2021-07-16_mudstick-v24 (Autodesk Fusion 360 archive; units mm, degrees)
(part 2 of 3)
sketch "Sketch19" plane through (2.9, 0, 0) normal (-1, 0, 0) x axis (0, -1, 0)
  line L1 (27.1, 161.8575) -> (13.5, 161.8575)
  line L2 (30.1, 117.8575) -> (30.1, 158.8575)
  line L3 (10.5, 114.8575) -> (27.1, 114.8575)
  line L4 (10.5, 114.75) -> (10.5, 114.8575)
  line L5 (10.1, 114.75) -> (10.5, 114.75)
  line L6 (10.1, 2.0302) -> (10.1, 114.75)
  line L7 (10.5, 2.0302) -> (10.1, 2.0302)
  line L8 (10.5, -11) -> (10.5, 2.0302)
  line L9 (27.35, -11) -> (10.5, -11)
  line L10 (27.35, -7.85) -> (27.35, -11)
  line L11 (52.65, -7.85) -> (27.35, -7.85)
  line L12 (52.65, -11) -> (52.65, -7.85)
  line L13 (73, -11) -> (52.65, -11)
  line L14 (73, 233.5398) -> (73, -11)
  line L15 (52.65, 233.5398) -> (73, 233.5398)
  line L16 (52.65, 230.3898) -> (52.65, 233.5398)
  line L17 (27.35, 230.3898) -> (52.65, 230.3898)
  line L18 (27.35, 233.5398) -> (27.35, 230.3898)
  line L19 (4, 233.5398) -> (27.35, 233.5398)
  line L20 (4, 181.5398) -> (4, 233.5398)
  line L21 (7.5, 178.5398) -> (7, 178.5398)
  line L22 (10.5, 164.8575) -> (10.5, 175.5398)
  line L23 (105.1, 15.7802) -> (85.1, 15.7802)
  line L24 (105.1, 35.7802) -> (105.1, 15.7802)
  line L25 (85.1, 35.7802) -> (105.1, 35.7802)
  line L26 (85.1, 15.7802) -> (85.1, 35.7802)
  line L27 (25, 6.7802) -> (65, 6.7802)
  line L28 (105.1, 25.7802) -> (85.1, 25.7802)
  arc A1 centre (13.5, 164.8575) radius 3 clockwise from (13.5, 161.8575) to (10.5, 164.8575)
  arc A2 centre (27.1, 158.8575) radius 3 clockwise from (27.1, 161.8575) to (30.1, 158.8575)
  arc A3 centre (27.1, 117.8575) radius 3 clockwise from (30.1, 117.8575) to (27.1, 114.8575)
  arc A4 centre (7, 181.5398) radius 3 clockwise from (7, 178.5398) to (4, 181.5398)
  arc A5 centre (7.5, 175.5398) radius 3 clockwise from (7.5, 178.5398) to (10.5, 175.5398)
  circle C1 centre (12, 223.5398) radius 2.125
  circle C2 centre (16.5, -5) radius 2.125
  circle C3 centre (63.5, -5) radius 2.125
  circle C4 centre (68, 223.5398) radius 2.125
  circle C5 centre (65, 6.7802) radius 1.65
  circle C6 centre (25, 6.7802) radius 1.65
  circle C7 centre (65, 44.7802) radius 1.65
  circle C8 centre (25, 44.7802) radius 1.65
  point P43 (65, 6.7802)
  point P45 (65, 6.7802)
  point P44 (25, 6.7802)
  point P46 (25, 6.7802)
  point P47 (85.1, 25.7802)
  point P48 (105.1, 25.7802)
  point P40 (105.1, 35.7802)
  point P41 (85.1, 35.7802)
  point P42 (0.1, 1.7802)
  horizontal L23
  vertical L24
  horizontal L25
  vertical L26
  equal L25 L26
  coincident P43 P45
  coincident P44 P46
  horizontal L27
  equal C5 C6
  midpoint L26 P47
  midpoint L24 P48
  symmetric C5 L28 C7
  symmetric C6 L28 C8
  dimension "d552" distance P40 P41 = 20
  dimension "d553" distance L23 P42 = 14
  dimension "d554" diameter C5 = 3.3
  dimension "d555" distance L23 L27 = 9
  dimension "d556" distance L14 P43 = 8
  dimension "d557" distance P45 P46 = 40
  dimension "d558" distance L26 P42 = 85
extrude "Extrude33" cut sketch "Sketch19" profile of C5 C6 C7 C8 to an object
fillet "Fillet23" radius 2
offset_faces "OffsetFaces1" distance -0.25
fillet "Fillet24" radius 2
fillet "Fillet25" radius 2
fillet "Fillet26" radius 3
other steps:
joint_origin "JointOrigin1"
joint_origin "JointOrigin2"
joint_origin "JointOrigin3"
named bodies: "Home Plate", "Canister", "Nozzle", "Drive", "Drive Cap", "Drive Housing", "Outer Plunger", "Ball Screw", "Inner Plunger", "Lower Cup", "West Wing", "East Wing", "Drive Housing (1)", "Handle"

design "Mudstick Plate" references "PULL OUT DOWEL 6x16 97355A292", "Hotplate Pogo Drop", "BHCS M4x10 92095A190", "BHCS M4 x 25 92095A197"
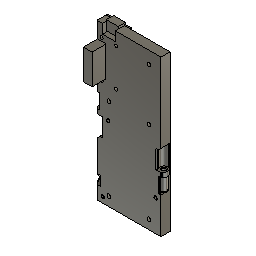
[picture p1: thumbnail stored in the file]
parameter "t_sheet_MAIN" = 7.9375 (= "5 / 16 * 1")
parameter "extrusion_w" = 20
parameter "extrusion_h" = 60
parameter "r_cutoutTool" = 2.05 (= "4.1 mm / 2")
parameter "od_bearings" = 13
parameter "id_bearings" = 4
parameter "t_bearings" = 5
parameter "preload" = 0.15
parameter "hw_m3_thru" = 3.5
parameter "hw_m3_thread" = 2.5
parameter "hw_m3_head" = 5.5
parameter "hw_m3_headheight" = 3
parameter "hw_m3_flathead" = 6
parameter "hw_m3_buttonhead" = 5.7
parameter "hw_m3_washer" = 7
parameter "hw_m3hex_d" = 5.5
parameter "hw_m3hex_t" = 4
parameter "hw_m3i_d" = 5.4
parameter "hw_m3i_l" = 3.8
parameter "hw_m3ichamfer" = 0.95 (= "( hw_m3i_d - hw_m3_thru ) / 2")
parameter "hw_m4_thru" = 4.25
parameter "hw_m4_head" = 7
parameter "hw_m4_headheight" = 4
parameter "hw_m4hex_d" = 7
parameter "hw_m4hex_t" = 5.2
parameter "hw_m4i_d" = 6
parameter "hw_m4i_l" = 4.8
parameter "hw_m4ichamfer" = 0.875 (= "( hw_m4i_d - hw_m4_thru ) / 2")
parameter "hw_m5_thread" = 4.2
parameter "hw_m5_head" = 8.5
parameter "hw_m5_washer" = 10
parameter "hw_m5_thru" = 5.25
parameter "hw_m6_thru" = 6.5
parameter "hw_m6_head" = 10
parameter "hw_m6_flathead" = 12
parameter "hw_m6_buttonhead" = 10.5
parameter "hw_m6_washer" = 12
parameter "p_belt" = 1.4
parameter "w_belt" = 10
parameter "t_belt" = 1.4
parameter "belt_pdo_toothside" = 1.15
parameter "belt_pdo_backside" = 0.25
parameter "t_m4_washer" = 0.85
parameter "flex_t" = 2.54
parameter "flex_l" = 5
parameter "t_motor_plates" = 6 comment "5/16 Phenolic"
parameter "swap_center_distance" = 40
parameter "pd_swap_drive" = 57.2958 (= "( nt_swap_drive * 2 / PI ) * 1 mm")
parameter "pd_swap_pinion" = 10.1859 (= "( nt_swap_pinion * 2 / PI ) * 1 mm")
parameter "od_mintool" = 2.1
parameter "t_sheet_THIN" = 5
parameter "c2c_spanners" = 14
parameter "c2c_height_pts" = 75
parameter "d954" = 1.7
parameter "d1221" = 5
parameter "d1747" = 9
parameter "d1748" = 5.5 (= "t_sheet_THIN + 0.5 mm")
parameter "d1761" = 2
parameter "d1917" = 5
sketch "Plan" plane through (0, 0, 0) normal (0, 0, 1) x axis (1, 0, 0)
  line L1 (-35, -5) -> (35, -5)
  line L2 (35, 5) -> (-35, 5)
  line L3 (35, -5) -> (35, 5)
  line L4 (-32.8378, -7.9826) -> (-38.2756, -10.5183)
  line L5 (-39.5997, 6.5183) -> (-32.8378, -7.9826)
  line L6 (-45.0375, 3.9826) -> (-39.5997, 6.5183)
  line L7 (-38.2756, -10.5183) -> (-45.0375, 3.9826)
  line L8 (-35.5567, -9.2505) -> (-42.3186, 5.2505)
  line L9 (-35, -3.8) -> (-35.5, -3.8)
  line L10 (-35, 3.8) -> (-35.5, 3.8)
  line L11 (-35.5, -3.8) -> (-35.5, 3.8)
  line L12 (-35.5, 0) -> (-35, 0)
  line L13 (0, -5) -> (0, 5)
  line L14 (35, 0) -> (-35, 0)
  line L15 (-33.25, 3) -> (-35, 3)
  line L16 (-30.25, -5) -> (-30.25, 0)
  line L17 (-32.75, -20) -> (-32.75, -12.9033)
  line L18 (-47.0948, -20) -> (-32.75, -20)
  line L19 (-58.5, 4.4586) -> (-47.0948, -20)
  line L20 (-58.5, 18.5) -> (-58.5, 4.4586)
  line L21 (-36.5156, 6.5) -> (0, 6.5)
  line L22 (-32.75, -12.9033) -> (-40.8544, 4.4768)
  line L23 (40, -5.1) -> (-40, -5.1)
  line L24 (40, -17.8) -> (40, -5.1)
  line L25 (-40, -17.8) -> (40, -17.8)
  line L26 (-40, -5.1) -> (-40, -17.8)
  line L27 (0, -17.8) -> (0, -5.1)
  line L28 (45, 18.5) -> (0, 18.5)
  line L29 (37.0839, 1.7621) -> (34.359, -5.7245)
  line L30 (39.0574, -7.4346) -> (34.359, -5.7245)
  line L31 (45.3388, -0.0273) -> (39.0574, -7.4346)
  line L32 (40, 4.5) -> (40, 24.5)
  line L33 (43.9547, 25.1) -> (46.9208, 5.55)
  line L34 (45, 4.5) -> (45, 18.5)
  line L35 (45, 4.5) -> (40, 4.5)
  line L36 (36, 6.5) -> (0, 6.5)
  line L37 (36, 4.5) -> (36, 6.5)
  line L38 (45, 0.5) -> (45, 4.5)
  line L39 (40, 0.5) -> (45, 0.5)
  line L40 (-58.5, 18.5) -> (0, 18.5)
  line L41 (0, 18.5) -> (0, 6.5)
  line L42 (-36.5156, 6.5) -> (-40.8544, 4.4768)
  line L43 (-35, 6.5) -> (-36.5156, 6.5)
  line L44 (-35, 18.5) -> (-35, 6.5)
  line L45 (35, 18.5) -> (35, 6.5)
  line L46 (40, 0.5) -> (36, 0.5)
  line L47 (40, 7.6754) -> (42.75, 6.0877)
  line L48 (37.25, 6.0877) -> (40, 7.6754)
  line L49 (37.25, 2.9123) -> (37.25, 6.0877)
  line L50 (40, 1.3246) -> (37.25, 2.9123)
  line L51 (42.75, 2.9123) -> (40, 1.3246)
  line L52 (42.75, 6.0877) -> (42.75, 2.9123)
  line L53 (43.1754, 24.5) -> (41.5877, 21.75)
  line L54 (41.5877, 27.25) -> (43.1754, 24.5)
  line L55 (38.4123, 27.25) -> (41.5877, 27.25)
  line L56 (36.8246, 24.5) -> (38.4123, 27.25)
  line L57 (38.4123, 21.75) -> (36.8246, 24.5)
  line L58 (41.5877, 21.75) -> (38.4123, 21.75)
  line L59 (36, 24.5) -> (36, 6.5)
  line L60 (36, 4.5) -> (36, 0.5)
  line L61 (20.3431, 18.5) -> (32.3431, 6.5)
  line L62 (-15, 11.5) -> (-35, 11.5)
  line L63 (-15, 18.5) -> (-15, 11.5)
  line L64 (-35, 2.4367) -> (-35, -5)
  line L65 (-35, 5) -> (-35, 3)
  line L66 (-33.25, -5) -> (-33.25, -3)
  line L67 (33.25, 3) -> (35, 3)
  line L68 (30.25, -5) -> (30.25, 0)
  line L69 (33.25, -5) -> (33.25, -3)
  line L70 (-35, 3) -> (-35, 2.4367)
  arc A1 centre (-32.1029, 0) radius 5.0971 clockwise from (-35.5, -3.8) to (-35.5, 3.8)
  circle C1 centre (-33.25, 0) radius 3
  circle C2 centre (33.25, 0) radius 3
  circle C3 centre (40, 4.5) radius 1.625
  circle C4 centre (40, 24.5) radius 1.625
  circle C5 centre (40, 24.5) radius 4
  circle C6 centre (40, 4.5) radius 4
  arc A2 centre (40, 4.5) radius 7 clockwise from (46.9208, 5.55) to (45.3388, -0.0273)
  circle C7 centre (-33.25, 0) radius 4.25
  circle C8 centre (-33.25, 0) radius 2.125
  circle C9 centre (33.25, 0) radius 3
  circle C10 centre (33.25, 0) radius 2.125
  circle C11 centre (33.25, 0) radius 4.25
  point P10 (-42.3186, 5.2505)
  point P11 (-35.5567, -9.2505)
  point P15 (-35, -3.8)
  point P16 (-35, 3.8)
  point P14 (-35.5, -3.8)
  point P17 (-35.5, -3.8)
  point P19 (-35.5, 0)
  point P20 (-37.2, 0)
  point P21 (0, 5)
  point P22 (0, -5)
  point P1 (0, 0)
  point P24 (35, 0)
  point P23 (-33.25, 0)
  point P25 (-35, 3)
  point P26 (-30.25, -5)
  point P27 (-38.9377, -2)
  point P41 (0, -5.1)
  point P42 (0, -17.8)
  point P52 (40, 24.5)
  point P54 (40, 24.5)
  point P49 (37.0839, 1.7621)
  point P58 (45.3388, -0.0273)
  point P51 (45.3388, -0.0273)
  point P60 (43.9547, 25.1)
  point P61 (40, 28.5)
  point P56 (40, 4.5)
  point P63 (40, 4.5)
  point P62 (45, 4.5)
  point P64 (45, 4.5)
  point P66 (36, 4.5)
  point P68 (40, 0.5)
  point P36 (0, 6.5)
  point P45 (0, 6.5)
  point P33 (-58.5, 18.5)
  point P69 (-58.5, 18.5)
  point P34 (-36.5156, 6.5)
  point P70 (-36.5156, 6.5)
  point P28 (-32.75, -12.9033)
  point P29 (-32.75, -12.9033)
  point P72 (-35, 18.5)
  point P4 (-35, 5)
  point P73 (35, 6.5)
  point P74 (35, 18.5)
  point P5 (35, 5)
  point P76 (40, 0.5)
  point P47 (40, 4.5)
  point P83 (40, 4.5)
  point P90 (40, 24.5)
  point P57 (40, 4.5)
  point P55 (40, 4.5)
  point P91 (36, 24.5)
  point P92 (36, 4.5)
  point P93 (32.3431, 6.5)
  point P94 (20.3431, 18.5)
  point P95 (-35, 11.5)
  point P97 (-15, 18.5)
  point P100 (-35, 2.4367)
  point P18 (-35, 0)
  point P101 (-33.25, 3)
  point P102 (-33.25, -3)
  point P103 (-33.25, -5)
  point P98 (-33.25, 0)
  point P104 (-30.25, 0)
  point P107 (35, 3)
  point P111 (30.25, -5)
  point P108 (33.25, 3)
  point P112 (33.25, -3)
  point P113 (33.25, -5)
  point P110 (30.25, 0)
  point P3 (-35, -5)
  point P6 (-38.2756, -10.5183)
  point P9 (-45.0375, 3.9826)
  point P8 (-39.5997, 6.5183)
  point P13 (-35.5, 3.8)
  point P37 (-40, -5.1)
  point P38 (40, -5.1)
  point P44 (33.25, 0)
  point P48 (34.359, -5.7245)
  point P50 (39.0574, -7.4346)
  point P53 (40, 24.5)
  point P67 (45, 0.5)
  point P43 (0, 18.5)
  point P79 (37.25, 6.0877)
  point P86 (41.5877, 27.25)
  point P96 (-15, 11.5)
  point P71 (-35, 6.5)
  horizontal L1
  vertical L64
  horizontal L2
  vertical L3
  perpendicular L4 L5
  parallel L4 L6
  parallel L5 L7
  midpoint L6 P10
  midpoint L4 P11
  coincident P15 L64
  perpendicular L9 L64
  coincident P16 L64
  perpendicular L10 L64
  perpendicular L10 L11
  coincident P14 P17
  perpendicular L12 L64
  midpoint L11 P19
  midpoint A1 P20
  midpoint L2 P21
  midpoint L1 P22
  midpoint P1 L13
  midpoint L3 P24
  coincident P23 L14
  coincident P25 L64
  perpendicular L15 L64
  coincident L1 P26
  perpendicular L1 L16
  midpoint L8 P27
  vertical L17
  perpendicular L17 L18
  vertical L20
  horizontal L23
  vertical L24
  horizontal L25
  vertical L26
  midpoint L23 P41
  midpoint L25 P42
  coincident P1 L27
  horizontal L21
  symmetric L13 C1 C2
  perpendicular L29 L30
  concentric C4 C5
  coincident P52 P54
  tangent C2 L29
  vertical L32
  coincident P49 C6
  coincident L31 P58
  coincident P51 P58
  tangent L31 A2
  coincident C5 P60
  tangent C5 L33
  tangent A2 L33
  coincident C5 P61
  coincident L32 P61
  perpendicular L28 L34
  coincident P56 P63
  perpendicular L32 L35
  coincident P62 P64
  perpendicular L36 L37
  coincident C6 P66
  coincident L35 P66
  perpendicular L35 L38
  perpendicular L34 L39
  coincident C6 P68
  coincident L32 P68
  coincident P36 P45
  coincident P33 P69
  perpendicular L28 L41
  coincident P1 L41
  horizontal L28
  horizontal L36
  horizontal L40
  perpendicular L5 L42
  coincident P34 P70
  parallel L8 L22
  coincident P28 P29
  parallel L8 L19
  parallel L21 L43
  coincident L40 P72
  perpendicular L40 L44
  coincident P4 L44
  coincident L36 P73
  coincident L28 P74
  perpendicular L28 L45
  coincident P5 L45
  equal C5 C6
  perpendicular L37 L46
  coincident P68 P76
  coincident P47 P83
  vertical L52
  coincident P52 P90
  horizontal L58
  coincident P57 P83
  coincident P55 P57
  coincident P47 P56
  coincident C5 P91
  perpendicular L46 L60
  coincident P66 P92
  coincident L36 P93
  coincident L28 P94
  tangent C6 L61
  coincident L44 P95
  perpendicular L41 L62
  coincident L40 P97
  perpendicular L40 L63
  tangent L5 C1
  concentric C1 C7
  concentric C1 C8
  coincident C1 P100
  collinear L64 L65
  coincident P18 L64
  coincident C1 P101
  coincident C1 P102
  coincident L1 P103
  perpendicular L1 L66
  coincident P98 L66
  coincident C1 P104
  symmetric L13 C1 C9
  symmetric L13 P25 P107
  symmetric L13 P26 P111
  symmetric L13 C7 C11
  symmetric L13 C8 C10
  symmetric L13 P101 P108
  symmetric L13 P102 P112
  symmetric L13 P103 P113
  symmetric L13 P104 P110
  dimension "d1706" distance P3 P4 = 10
  dimension "d1707" distance P6 P9 = 16
  dimension "d1708" distance P8 P9 = 6
  dimension "d1709" distance P13 P17 = 7.6
  dimension "d1710" distance P20 L64 = 2.2
  dimension "d1711" distance P13 P16 = 0.5
  dimension "d1712" distance P1 L64 = 35
  dimension "d1713" diameter C1 = 6
  dimension "d1714" distance P23 L64 = 1.75
  dimension "d1715" distance P23 L16 = 3 (= "d1713 / 2")
  dimension "d1716" distance P23 L15 = 3 (= "d1715")
  dimension "d1717" angle L8 L64 = 25
  dimension "d1723" distance L14 P27 = 2
  dimension "d1731" distance L17 L64 = 2.25
  dimension "d1732" distance L14 L18 = 20
  dimension "d1734" distance P27 L22 = 1
  dimension "d1763" distance P37 P38 = 80
  dimension "d1764" distance P41 P42 = 12.7
  dimension "d1765" distance L1 L23 = 0.1
  dimension "d1796" diameter C3 = 3.25
  dimension "d1799" distance L3 P47 = 5
  dimension "d1800" diameter C4 = 3.25
  dimension "d1802" angle L3 L29 = 20
  dimension "d1803" distance P44 L30 = 5
  dimension "d1804" distance P48 P50 = 5
  dimension "d1805" = 8.2688
  dimension "d1806" distance P47 P53 = 20
  dimension "d1808" = 1.5
  dimension "d1809" diameter C6 = 8
  dimension "d1810" distance P44 P47 = 4.5
  dimension "d1811" radius A2 = 7
  dimension "d1827" distance P67 P68 = 5
  dimension "d1955" distance L14 L21 = 6.5
  dimension "d1988" distance P36 P43 = 12
  dimension "d1989" distance P4 L42 = 2
  dimension "d1990" distance P27 L19 = 15
  dimension "d2035" distance P79 L52 = 5.5
  dimension "d2036" distance P86 L58 = 5.5
  dimension "d2063" angle L32 L61 = 45
  dimension "d2100" distance P95 P96 = 20
  dimension "d2126" distance P71 L62 = 5
  dimension "d2129" diameter C7 = 8.5
  dimension "d2130" diameter C8 = 4.25
  dimension "d2131" radius A1 = 5.0971
  dimension "d2236" distance L20 P72 = 23.5
  dimension "d523" OffsetX = 0
  dimension "d524" OffsetY = 0
  dimension "d525" OffsetZ = 0
  dimension "d526" AngleZ = 0
  dimension "d567" OffsetX = 0
  dimension "d568" OffsetY = 0
  dimension "d569" OffsetZ = 0
  dimension "d570" AngleZ = 0
  dimension "d1892" alignAngle = 180
  dimension "d1893" alignOffsetX = 0
  dimension "d1894" alignOffsetY = 0
  dimension "d1895" alignOffsetZ = 1
  dimension "d1896" radius = 1.05 (= "od_mintool / 2")
  dimension "d1897" distance = 1.05 (= "d1896")
  dimension "d1898" radius = 1.05 (= "od_mintool / 2")
  dimension "d1899" distance = 1.05 (= "d1898")
  dimension "d1900" distance = 17
  dimension "d1901" distance = 15
  dimension "d1902" ProfileOffset = 0
  dimension "d1903" Side1Offset = 0
  dimension "d1904" TaperAngle = 0
  dimension "d1905" ProfileOffset = 0
  dimension "d1906" Side1Offset = 0
  dimension "d1907" TaperAngle = 0
  dimension "d1908" ProfileOffset = 0
  dimension "d1909" Side1Offset = 0
  dimension "d1910" TaperAngle = 0
  dimension "d1911" ProfileOffset = 0
  dimension "d1912" Side1Offset = 0
  dimension "d1913" TaperAngle = 0
  dimension "d1914" Side1Offset = 0
  dimension "d1915" TaperAngle = 0
  dimension "d1916" distance = 10
  dimension "d1918" distance = 5
  dimension "d1919" distance = 25
  dimension "d1921" TaperAngle = 0
  dimension "d1922" distance = -0.075
  dimension "d1923" angle = 45
  dimension "d1924" diameter = 2.1 (= "od_mintool")
  dimension "d1925" diameter = 2.1 (= "od_mintool")
  dimension "d1926" diameter = 2.1 (= "od_mintool")
  dimension "d1927" Side1Offset = 0
  dimension "d1928" TaperAngle = 0
  dimension "d1929" ProfileOffset = 0
  dimension "d1930" Side1Offset = 0
  dimension "d1931" TaperAngle = 0
  dimension "d1932" angle = 45
  dimension "d1933" diameter = 2.1 (= "od_mintool")
  dimension "d1934" diameter = 2.1 (= "od_mintool")
  dimension "d1935" Side1Offset = 0
  dimension "d1936" TaperAngle = 0
  dimension "d1937" distance = -0.075
  dimension "d1941" Side1Offset = 0
  dimension "d1942" TaperAngle = 0
  dimension "d1943" Side1Offset = 0
  dimension "d1944" TaperAngle = 0
  dimension "d1947" alignAngle = 0
  dimension "d1948" alignOffsetX = 0
  dimension "d1949" alignOffsetY = 0
  dimension "d1950" alignOffsetZ = 0
  dimension "d1951" alignAngle = 90
  dimension "d1952" alignOffsetX = 0
  dimension "d1953" alignOffsetY = 0
  dimension "d1954" alignOffsetZ = 0
  dimension "d1958" ProfileOffset = 0
  dimension "d1959" Side1Offset = 0
  dimension "d1960" TaperAngle = 0
  dimension "d1961" distance = -0.075
  dimension "d1962" ProfileOffset = 0
  dimension "d1963" Side1Offset = 0
  dimension "d1964" TaperAngle = 0
  dimension "d1965" distance = -0.075
  dimension "d1966" distance = 67
  dimension "d1967" distance = 33
  dimension "d1968" diameter = 2.5
  dimension "d1969" distance = 4
  dimension "d1970" distance = 29
  dimension "d1971" distance = 34
  dimension "d1972" distance = 54
  dimension "d1973" distance = 4
  dimension "d1974" distance = 3
  dimension "d1975" distance = 3
  dimension "d1976" distance = 5
  dimension "d1977" distance = 5
  dimension "d1978" distance = 1
  dimension "d1979" distance = 1
  dimension "d1980" distance = 10
  dimension "d1981" distance = 10
  dimension "d1982" distance = 6
  dimension "d1983" ProfileOffset = 0
  dimension "d1984" Side1Offset = 0
  dimension "d1985" TaperAngle = 0
  dimension "d1987" Radius = 1.05 (= "od_mintool / 2")
  dimension "d1597" distance = 1.6
  dimension "d1598" distance = 67
  dimension "d1599" diameter = 4.25
  dimension "d1600" diameter = 3.3
  dimension "d1601" distance = 1
  dimension "d1602" distance = 1
  dimension "d1603" distance = 0.5
  dimension "d1604" distance = 12
  dimension "d1605" distance = 0.25
  dimension "d1606" distance = 0.25
  dimension "d1607" distance = 1
  dimension "d1608" distance = 8
  dimension "d1609" distance = 4.5
  dimension "d1610" distance = 4.5
  dimension "d1612" TaperAngle = 0
  dimension "d1613" AlongDistance = -53 (= "-20 mm - 33 mm")
  dimension "d1614" TaperAngle = 0
  dimension "d1615" ProfileOffset = 0.1
  dimension "d1616" Side1Offset = 0
  dimension "d1617" TaperAngle = 0
  dimension "d1618" leftDistance = 1
  dimension "d1619" distance = 67
  dimension "d1620" distance = 33
  dimension "d1621" distance = 0.5
  dimension "d1622" distance = 24.5
  dimension "d1623" diameter = 2.5
  dimension "d1624" distance = 4
  dimension "d1625" distance = 34
  dimension "d1626" distance = 54
  dimension "d1627" distance = 4
  dimension "d1628" distance = 29
  dimension "d1631" distance = 1
  dimension "d1633" distance = 3
  dimension "d1634" distance = 2.44 (= "d1643")
  dimension "d1635" diameter = 4
  dimension "d1636" distance = 15
  dimension "d1637" distance = 3
  dimension "d1638" distance = 15
  dimension "d1639" distance = 2
  dimension "d1640" Side1Offset = 0
  dimension "d1641" TaperAngle = 0
  dimension "d1642" distance = 2.44
  dimension "d1643" distance = 2.44
  dimension "d1644" AlongDistance = -16
  dimension "d1645" TaperAngle = 0
  dimension "d1647" Radius = 1
  dimension "d1649" Radius = 1
  dimension "d1651" Radius = 5
  dimension "d1653" Radius = 1
  dimension "d1654" diameter = 12
  dimension "d1655" Side1Offset = 0
  dimension "d1656" TaperAngle = 0
  dimension "d1658" Radius = 2
  dimension "d1659" distance = 20
  dimension "d1660" distance = 5
  dimension "d1661" distance = 5
  dimension "d981" distance = 15 (= "( 30 / 2 ) * 1 mm")
  dimension "d982" distance = 8
  dimension "d983" distance = 1.5
  dimension "d984" distance = 0.3
  dimension "d985" distance = 4
  dimension "d987" distance = 1
  dimension "d988" distance = 7.5
  dimension "d989" distance = 5
  dimension "d990" distance = 0.5
  dimension "d991" AlongAngle = 60
  dimension "d992" AgainstAngle = 60
  dimension "d993" distance = 4
  dimension "d994" angle = 60
  dimension "d995" angle = 60 (= "d994")
  dimension "d1004" diameter = 6.5
  dimension "d1005" distance = 1.5
  dimension "d1006" AlongDistance = -10
  dimension "d1007" TaperAngle = 0
  dimension "d1008" Side1Offset = 0
  dimension "d1009" TaperAngle = 0
  dimension "d1010" ProfileOffset = 0
  dimension "d1011" AlongDistance = -0.5
  dimension "d1012" TaperAngle = 0
  dimension "d1013" AlongDistance = 2.5
  dimension "d1014" TaperAngle = 0
  dimension "d1015" leftDistance = 0.25
  dimension "d1017" Radius = 1
  dimension "d1019" TotalAngle = 360
  dimension "d1020" ProfileOffset = 0
  dimension "d1021" Side1Offset = 0
  dimension "d1022" TaperAngle = 0
  dimension "d1028" angle = 25
  dimension "d1029" ProfileOffset = 0
  dimension "d1030" Side1Offset = 0
  dimension "d1031" TaperAngle = 0
  dimension "d1032" ProfileOffset = 0
  dimension "d1034" TaperAngle = 0
  dimension "d1035" Side1Offset = 0
  dimension "d1036" distance = 3
  dimension "d1037" leftDistance = 3
  dimension "d1038" rightDistance = 17.25
  dimension "d1039" Side1Offset = 0
  dimension "d1040" TaperAngle = 0
  dimension "d1042" TotalAngle = 360
  dimension "d1043" Side1Offset = 0
  dimension "d1044" TaperAngle = 2
  dimension "d1045" angle = 1
  dimension "d1047" Side1Offset = 0
  dimension "d1048" TaperAngle = 0
  dimension "d1049" distance = -1 (= "0 mm - 1 mm")
  dimension "d1051" TotalAngle = 360
  dimension "d1053" angle = 43.731
  dimension "d1054" angle = 28 (= "d1055 - d1056")
  dimension "d1055" angle = 50 (= "d1028 * 2")
  dimension "d1056" angle = 22
  dimension "d1058" Radius = 2
  dimension "d1060" Radius = 2
  dimension "d1061" alignAngle = 0
  dimension "d1062" alignOffsetX = 0
  dimension "d1063" alignOffsetY = 0
  dimension "d1064" alignOffsetZ = 0
  dimension "d1082" distance = 0.8
  dimension "d1084" distance = 0.8
  dimension "d1085" distance = 1.2
  dimension "d1086" distance = 1.2
  dimension "d1087" distance = 0.1
  dimension "d1093" Radius = 0.5
  dimension "d1095" Radius = 0.5
  dimension "d1097" Radius = 2
  dimension "d1103" distance = 1.3
  dimension "d1105" TotalAngle = 360
  dimension "d1106" distance = 2.75 (= "hw_m3hex_d / 2")
  dimension "d1107" distance = 1.75 (= "hw_m3_thru / 2")
  dimension "d1108" angle = 45
  dimension "d1109" distance = 3.6
  dimension "d1110" distance = 20
  dimension "d1111" distance = 1.7
  dimension "d1112" AlongAngle = 360
  dimension "d1113" Side1Offset = 0
  dimension "d1114" TaperAngle = 0
  dimension "d1116" TotalAngle = 360
  dimension "d1118" Radius = 2
  dimension "d1120" distance = 3.175 (= "1 / 8 * 1")
  dimension "d1121" radius = 12
  dimension "d1123" radius = 6.5
  dimension "d1124" angle = 60
  dimension "d1126" distance = 2.8797 (= "13 / 64 * 1  / 2 + 0.3 mm")
  dimension "d1127" distance = 9.5563 (= "7 / 32 * 1  + 4 mm")
  dimension "d1128" AlongDistance = -6
  dimension "d1129" diameter = 3.475 (= "1 / 8 * 1  + 0.3 mm")
  dimension "d1130" diameter = 1.7875 (= "1 / 16 * 1  + 0.2 mm")
  dimension "d1141" TwistAngle = 0
  dimension "d1142" TaperAngle = 0
  dimension "d1143" angle = 51
  dimension "d1144" distance = 2.8797 (= "d1126")
  dimension "d1145" diameter = 1.7875 (= "1 / 16 * 1  + 0.2 mm")
  dimension "d1150" TwistAngle = 0
  dimension "d1151" TaperAngle = 0
  dimension "d1152" distance = 1.7875 (= "1 / 16 * 1  + 0.2 mm")
  dimension "d1153" Side1Offset = 0
  dimension "d1154" TaperAngle = 0
  dimension "d1155" AlongDistance = -4
  dimension "d1156" TaperAngle = 0
  dimension "d1157" diameter = 5.3594 (= "13 / 64 * 1  + 0.2 mm")
  dimension "d1158" AlongDistance = 1.5
  dimension "d1159" TaperAngle = 0
  dimension "d1164" TwistAngle = 0
  dimension "d1165" TaperAngle = 0
  dimension "d1167" mirrorStitchTolerance = 0.1
  dimension "d1169" Radius = 0.4
  dimension "d1170" distance = 11
  dimension "d1171" distance = 1.0938 (= "( 1 / 16 * 1  + 0.2 mm ) / 2 + 0.2 mm")
  dimension "d1172" distance = 1.7
  dimension "d1173" distance = 1.7
  dimension "d1174" Side1Offset = 0
  dimension "d1175" TaperAngle = 0
  dimension "d1176" Side2Offset = -1
  dimension "d1177" Side2TaperAngle = 0
  dimension "d1179" mirrorStitchTolerance = 0.1
  dimension "d1181" Radius = 0.5
  dimension "d1182" alignAngle = 0
  dimension "d1183" alignOffsetX = 0
  dimension "d1184" alignOffsetY = 0
  dimension "d1185" alignOffsetZ = 0
  dimension "d1186" leftDistance = 0.75
  dimension "d1187" rightDistance = 3
  dimension "d1189" Radius = 12
  dimension "d1191" Radius = 2
  dimension "d1193" Radius = 0.5
  dimension "d1195" Radius = 0.5
  dimension "d1197" Radius = 0.5
  dimension "d1198" alignAngle = 0
  dimension "d1199" alignOffsetX = 0
  dimension "d1200" alignOffsetY = 0
  dimension "d1201" alignOffsetZ = 0
  dimension "d1202" distance = 13.5
sketch "Elevation" plane through (0, 0, 0) normal (0, 1, 0) x axis (1, 0, 0)
  line L1 (35, 0) -> (-35, 0)
  line L2 (35, -115) -> (35, 0)
  line L3 (-35, -115) -> (35, -115)
  line L4 (-35, 0) -> (-35, -115)
  line L5 (35, -10.5) -> (-35, -10.5)
  line L6 (-35, -15.5) -> (35, -15.5)
  line L7 (35, -24.5) -> (-35, -24.5)
  line L8 (-35, -29.5) -> (35, -29.5)
  line L9 (35, -85.5) -> (-35, -85.5)
  line L10 (-35, -90.5) -> (35, -90.5)
  line L11 (35, -99.5) -> (-35, -99.5)
  line L12 (-35, -104.5) -> (35, -104.5)
  line L13 (35, -40) -> (-35, -40)
  line L14 (35, -45) -> (-35, -45)
  line L15 (0, -90.5) -> (0, -99.5)
  line L16 (0, -24.5) -> (0, -15.5)
  line L17 (-35, 0) -> (35, 0)
  line L18 (0, -29.5) -> (0, -40)
  line L19 (0, -24.5) -> (0, -29.5)
  line L20 (0, -10.5) -> (0, -15.5)
  line L21 (0, -85.5) -> (0, -90.5)
  line L22 (0, -104.5) -> (0, -99.5)
  line L23 (25, -95) -> (-30, -95)
  line L24 (25, -20) -> (25, -95)
  line L25 (-30, -20) -> (25, -20)
  line L26 (-30, -95) -> (-30, -20)
  line L27 (-35, -50.5) -> (35, -50.5)
  line L28 (35, -55.5) -> (-35, -55.5)
  line L29 (0, -55.5) -> (0, -50.5)
  line L30 (0, -50.5) -> (0, -45)
  line L31 (-35.5, -78) -> (-56.5, -78)
  line L32 (-35.5, -37) -> (-35.5, -78)
  line L33 (-56.5, -37) -> (-35.5, -37)
  line L34 (-41, -82.25) -> (-51, -82.25)
  line L35 (-41, -32.75) -> (-41, -82.25)
  line L36 (-51, -32.75) -> (-41, -32.75)
  line L37 (-51, -82.25) -> (-51, -32.75)
  line L38 (-46, -57.5) -> (-46, -82.25)
  line L39 (-35.5, -57.5) -> (-46, -57.5)
  line L40 (-56.5, -85.5) -> (-56.5, -78)
  line L41 (-35, -85.5) -> (-56.5, -85.5)
  line L42 (-56.5, -29.5) -> (-35, -29.5)
  line L43 (-56.5, -37) -> (-56.5, -29.5)
  line L44 (-47.8246, -82.25) -> (-49.4123, -85)
  line L45 (-49.4123, -79.5) -> (-47.8246, -82.25)
  line L46 (-52.5877, -79.5) -> (-49.4123, -79.5)
  line L47 (-54.1754, -82.25) -> (-52.5877, -79.5)
  line L48 (-52.5877, -85) -> (-54.1754, -82.25)
  line L49 (-49.4123, -85) -> (-52.5877, -85)
  line L50 (-44.1754, -82.25) -> (-42.5877, -79.5)
  line L51 (-42.5877, -85) -> (-44.1754, -82.25)
  line L52 (-39.4123, -85) -> (-42.5877, -85)
  line L53 (-37.8246, -82.25) -> (-39.4123, -85)
  line L54 (-39.4123, -79.5) -> (-37.8246, -82.25)
  line L55 (-42.5877, -79.5) -> (-39.4123, -79.5)
  line L56 (-37.8246, -32.75) -> (-39.4123, -30)
  line L57 (-39.4123, -35.5) -> (-37.8246, -32.75)
  line L58 (-42.5877, -35.5) -> (-39.4123, -35.5)
  line L59 (-44.1754, -32.75) -> (-42.5877, -35.5)
  line L60 (-39.4123, -30) -> (-42.5877, -30)
  line L61 (-42.5877, -30) -> (-44.1754, -32.75)
  line L62 (-52.5877, -35.5) -> (-49.4123, -35.5)
  line L63 (-54.1754, -32.75) -> (-52.5877, -35.5)
  line L64 (-52.5877, -30) -> (-54.1754, -32.75)
  line L65 (-49.4123, -30) -> (-52.5877, -30)
  line L66 (-49.4123, -35.5) -> (-47.8246, -32.75)
  line L67 (-47.8246, -32.75) -> (-49.4123, -30)
  line L68 (-47, -80.75) -> (-47, -78)
  line L69 (-45, -78) -> (-45, -80.75)
  line L70 (-46, -80.75) -> (-46, -78)
  line L71 (-47, -34.25) -> (-47, -37)
  line L72 (-45, -37) -> (-45, -34.25)
  circle C1 centre (-51, -82.25) radius 1.625
  circle C2 centre (-41, -82.25) radius 1.625
  circle C3 centre (-41, -32.75) radius 1.625
  circle C4 centre (-51, -32.75) radius 1.625
  arc A1 centre (-46, -80.75) radius 1 clockwise from (-45, -80.75) to (-47, -80.75)
  arc A2 centre (-46, -78) radius 1 clockwise from (-47, -78) to (-45, -78)
  arc A3 centre (-46, -34.25) radius 1 clockwise from (-47, -34.25) to (-45, -34.25)
  arc A4 centre (-46, -37) radius 1 clockwise from (-45, -37) to (-47, -37)
  circle C5 centre (-23, -81) radius 1.65
  circle C6 centre (-23, -81) radius 4
  circle C7 centre (-29, -6) radius 1.65
  circle C8 centre (-29, -6) radius 4
  circle C9 centre (29, -33.75) radius 1.65
  circle C10 centre (29, -33.75) radius 4
  point P2 (35, 0)
  point P7 (-35, -10.5)
  point P8 (35, -10.5)
  point P9 (35, -15.5)
  point P10 (-35, -15.5)
  point P11 (-35, -24.5)
  point P12 (35, -24.5)
  point P13 (35, -29.5)
  point P14 (-35, -29.5)
  point P15 (-35, -85.5)
  point P16 (35, -85.5)
  point P17 (35, -90.5)
  point P18 (-35, -90.5)
  point P19 (-35, -99.5)
  point P20 (35, -99.5)
  point P21 (35, -104.5)
  point P22 (-35, -104.5)
  point P23 (-35, -40)
  point P24 (35, -40)
  point P25 (-35, -45)
  point P26 (35, -45)
  point P27 (0, -99.5)
  point P28 (0, -90.5)
  point P29 (0, -15.5)
  point P30 (0, -24.5)
  point P31 (0, -95)
  point P32 (0, -20)
  point P35 (0, -40)
  point P36 (0, -29.5)
  point P37 (0, -34.75)
  point P38 (0, -10.5)
  point P39 (0, -85.5)
  point P40 (0, -104.5)
  point P41 (0, -102)
  point P42 (0, -88)
  point P43 (0, -27)
  point P44 (0, -13)
  point P1 (0, 0)
  point P49 (0, 0)
  point P50 (35, -50.5)
  point P51 (-35, -50.5)
  point P52 (-35, -55.5)
  point P53 (35, -55.5)
  point P54 (0, -50.5)
  point P55 (0, -55.5)
  point P56 (0, -53)
  point P57 (0, -45)
  point P58 (0, -47.75)
  point P67 (-46, -82.25)
  point P70 (-41, -57.5)
  point P69 (-35.5, -57.5)
  point P71 (-46, -78)
  point P73 (-35, -85.5)
  point P62 (-56.5, -37)
  point P75 (-56.5, -37)
  point P63 (-51, -82.25)
  point P76 (-51, -82.25)
  point P64 (-41, -82.25)
  point P77 (-41, -82.25)
  point P84 (-51, -82.25)
  point P91 (-41, -82.25)
  point P78 (-49.4123, -85)
  point P103 (-49.4123, -30)
  point P79 (-47.8246, -82.25)
  point P104 (-47.8246, -32.75)
  point P80 (-49.4123, -79.5)
  point P99 (-49.4123, -35.5)
  point P81 (-52.5877, -79.5)
  point P100 (-52.5877, -35.5)
  point P82 (-54.1754, -82.25)
  point P101 (-54.1754, -32.75)
  point P83 (-52.5877, -85)
  point P102 (-52.5877, -30)
  point P85 (-42.5877, -79.5)
  point P96 (-42.5877, -35.5)
  point P86 (-44.1754, -82.25)
  point P97 (-44.1754, -32.75)
  point P87 (-42.5877, -85)
  point P98 (-42.5877, -30)
  point P88 (-39.4123, -85)
  point P93 (-39.4123, -30)
  point P89 (-37.8246, -82.25)
  point P94 (-37.8246, -32.75)
  point P90 (-39.4123, -79.5)
  point P95 (-39.4123, -35.5)
  point P111 (-46, -80.75)
  point P110 (-46, -78)
  point P106 (-47, -78)
  point P112 (-47, -37)
  point P107 (-47, -80.75)
  point P113 (-47, -34.25)
  point P108 (-45, -80.75)
  point P115 (-45, -34.25)
  point P109 (-45, -78)
  point P116 (-45, -37)
  point P118 (-35, 0)
  point P34 (-35, 0)
  point P59 (-56.5, -78)
  point P60 (-35.5, -78)
  point P61 (-35.5, -37)
  point P66 (-51, -32.75)
  point P121 (-29, -6)
  point P119 (-23, -81)
  point P123 (29, -33.75)
  point P4 (35, 0)
  point P5 (35, -115)
  point P6 (-35, -115)
  horizontal L1
  vertical L2
  horizontal L3
  vertical L4
  coincident P2 L2
  coincident L4 P7
  coincident L2 P8
  perpendicular L2 L5
  coincident L2 P9
  coincident L4 P10
  perpendicular L4 L6
  coincident L4 P11
  coincident L2 P12
  perpendicular L4 L7
  coincident L2 P13
  coincident L4 P14
  perpendicular L4 L8
  coincident L4 P15
  coincident L2 P16
  perpendicular L2 L9
  coincident L2 P17
  coincident L4 P18
  perpendicular L4 L10
  coincident L4 P19
  coincident L2 P20
  perpendicular L2 L11
  coincident L2 P21
  coincident L4 P22
  perpendicular L4 L12
  coincident L4 P23
  coincident L2 P24
  perpendicular L2 L13
  coincident L4 P25
  coincident L2 P26
  perpendicular L2 L14
  midpoint L11 P27
  midpoint L10 P28
  midpoint L6 P29
  perpendicular L6 L16
  coincident L7 P30
  midpoint L15 P31
  midpoint L16 P32
  midpoint L13 P35
  midpoint L8 P36
  midpoint L18 P37
  midpoint L5 P38
  midpoint L9 P39
  midpoint L12 P40
  midpoint L22 P41
  midpoint L21 P42
  midpoint L19 P43
  midpoint L20 P44
  horizontal L23
  vertical L24
  horizontal L25
  vertical L26
  coincident P32 L25
  coincident P31 L23
  coincident P1 P49
  coincident L2 P50
  coincident L4 P51
  perpendicular L4 L27
  coincident L4 P52
  coincident L2 P53
  perpendicular L2 L28
  midpoint L27 P54
  midpoint L28 P55
  midpoint L29 P56
  midpoint L14 P57
  midpoint L30 P58
  horizontal L31
  perpendicular L31 L32
  perpendicular L32 L33
  horizontal L34
  vertical L35
  horizontal L36
  vertical L37
  midpoint L34 P67
  perpendicular L31 L38
  perpendicular L38 L39
  midpoint L35 P70
  coincident L39 P70
  midpoint L32 P69
  midpoint L31 P71
  coincident L38 P71
  perpendicular L31 L40
  coincident L4 P73
  perpendicular L4 L41
  coincident P15 L41
  perpendicular L4 L42
  perpendicular L42 L43
  coincident P62 P75
  coincident L40 P75
  equal L40 L43
  coincident P63 P76
  coincident P64 P77
  equal C1 C2
  coincident P76 P84
  horizontal L49
  coincident P77 P91
  horizontal L52
  equal L49 L52
  symmetric L39 C1 C4
  symmetric L39 C2 C3
  symmetric L39 P78 P103
  symmetric L39 P79 P104
  symmetric L39 P80 P99
  symmetric L39 P81 P100
  symmetric L39 P82 P101
  symmetric L39 P83 P102
  symmetric L39 P85 P96
  symmetric L39 P86 P97
  symmetric L39 P87 P98
  symmetric L39 P88 P93
  symmetric L39 P89 P94
  symmetric L39 P90 P95
  tangent L68 A1
  tangent A1 L69
  parallel L68 L69
  tangent L69 A2
  tangent L68 A2
  coincident L38 P111
  perpendicular L31 L70
  coincident P71 P110
  symmetric L39 P106 P112
  symmetric L39 P107 P113
  symmetric L39 P108 P115
  symmetric L39 P109 P116
  symmetric L39 A1 A3
  symmetric L39 A2 A4
  coincident L4 P118
  coincident L1 P34
  concentric C5 C6
  concentric C7 C8
  concentric C9 C10
  dimension "d1742" distance L7 L8 = 5 (= "t_sheet_THIN")
  dimension "d1743" distance L5 L6 = 5 (= "t_sheet_THIN")
  dimension "d1744" distance L13 L14 = 5 (= "t_sheet_THIN")
  dimension "d1745" distance L9 L10 = 5 (= "t_sheet_THIN")
  dimension "d1746" distance L11 L12 = 5 (= "t_sheet_THIN")
  dimension "d1750" distance P32 L17 = 20
  dimension "d1751" distance P31 P32 = 75 (= "c2c_height_pts")
  dimension "d1752" distance L17 P37 = 34.75
  dimension "d1789" distance P43 P44 = 14 (= "c2c_spanners")
  dimension "d1791" distance P41 P42 = 14 (= "c2c_spanners")
  dimension "d1945" distance P31 L24 = 25
  dimension "d1946" distance P31 L26 = 30
  dimension "d1956" distance P54 P55 = 5 (= "t_sheet_THIN")
  dimension "d1957" distance L14 L27 = 5.5 (= "d1748")
  dimension "d2014" distance P59 P60 = 21
  dimension "d2015" distance P60 P61 = 41
  dimension "d2016" distance P63 P66 = 49.5
  dimension "d2017" distance P63 P64 = 10
  dimension "d2019" diameter C1 = 3.25
  dimension "d2020" distance P81 L49 = 5.5
  dimension "d2021" distance P107 L69 = 2
  dimension "d2022" distance L34 P111 = 1.5
  dimension "d2030" distance L4 L32 = 0.5
  dimension "d2031" distance L30 P62 = 56.5
  dimension "d2223" diameter C6 = 8
  dimension "d2224" diameter C5 = 3.3
  dimension "d2207" diameter C8 = 8
  dimension "d2208" diameter C7 = 3.3
  dimension "d2209" diameter C10 = 8
  dimension "d2210" diameter C9 = 3.3
  dimension "d2211" distance L4 P121 = 6
  dimension "d2212" distance L25 P121 = 14
  dimension "d2214" distance L4 P119 = 12
  dimension "d2216" distance L2 P123 = 6
  dimension "d2237" distance L3 P31 = 20 (= "d1750")
  dimension "d2238" distance P4 P5 = 115
  dimension "d2239" distance P5 P6 = 70
  dimension "d2241" distance P32 P58 = 27.75 (= "32.75 mm - 5 mm")
  dimension "d2242" distance P58 P123 = 14
  dimension "d2243" distance P31 P119 = 14
  dimension "d1938" diameter = 4.25
  dimension "d1940" diameter = 8
extrude "Extrude198" new body sketch "Plan" profile of L1 L65 L2 L3 C1 L15 L16 L29 C7 C8 L66 C9 C10 L67 C11 L68 L69 L70 to an object
extrude "Extrude199" sketch "Plan" profile of L1 L65 C1 L15 C7 C8 L66 L70 blind 16.25
extrude "Extrude200" sketch "Plan" profile of L1 L3 L29 C9 C10 L67 C11 L69 blind 16.25
extrude "Extrude201" sketch "Plan" profile of L3 L29 C6 L46 L60 C9 C10 C11 blind 5
extrude "Extrude202" sketch "Plan" profile of L1 L3 L29 C6 L46 L60 C9 C10 L67 C11 L68 L69 blind 20
extrude "Extrude203" sketch "Plan" profile of L3 C10 to an object
extrude "Extrude204" sketch "Plan" profile of L65 C1 C7 C8 L70 blind -5
extrude "Extrude205" sketch "Plan" profile of L1 L65 C1 L15 L16 C7 C8 L66 L70 blind -20
extrude "Extrude206" sketch "Plan" profile of L65 C8 to an object
chamfer "Chamfer26" distance 3
fillet "Fillet88" ChordLen 1
fillet "Fillet89" ChordLen 1
chamfer "Chamfer23" distance 0.5
fillet "Fillet90" ChordLen 1
fillet "Fillet91" ChordLen 1
sketch "Side Mount" plane through (-35, 0, 0) normal (-1, 0, 0) x axis (0, -1, 0)
  line L1 (-4.4874, 81.875) -> (-4.4874, 86.875)
  line L2 (-4.4874, 81.875) -> (-4.7601, 81.875)
  line L3 (-4.7601, 58.875) -> (-4.7601, 81.875)
  line L4 (-5, 115) -> (5, 115)
  line L5 (-5, 0) -> (-5, 115)
  line L6 (5, 0) -> (-5, 0)
  line L7 (5, 115) -> (5, 103.125)
  line L8 (-3.7071, 86.875) -> (-4.4874, 86.875)
  line L9 (-3.7071, 86.875) -> (-3.7071, 103.125)
  line L10 (5, 103.125) -> (-3.7071, 103.125)
  line L11 (0, 24.45) -> (0, 15.55)
  line L12 (4.0415, 24.45) -> (2.0207, 20.95)
  line L13 (2.0207, 27.95) -> (4.0415, 24.45)
  line L14 (-2.0207, 27.95) -> (2.0207, 27.95)
  line L15 (-4.0415, 24.45) -> (-2.0207, 27.95)
  line L16 (-2.0207, 20.95) -> (-4.0415, 24.45)
  line L17 (2.0207, 20.95) -> (-2.0207, 20.95)
  line L18 (-4.0415, 15.55) -> (-2.0207, 19.05)
  line L19 (4.0415, 15.55) -> (2.0207, 12.05)
  line L20 (2.0207, 12.05) -> (-2.0207, 12.05)
  line L21 (2.0207, 19.05) -> (4.0415, 15.55)
  line L22 (-2.0207, 19.05) -> (2.0207, 19.05)
  line L23 (-2.0207, 12.05) -> (-4.0415, 15.55)
  line L24 (-2.8868, 28.45) -> (-2.0207, 27.95)
  line L25 (-5, 28.45) -> (-2.8868, 28.45)
  line L26 (-2.8868, 20.45) -> (-2.0207, 20.95)
  line L27 (-5, 20.45) -> (-2.8868, 20.45)
  line L28 (-5, 20) -> (0, 20)
  line L29 (-2.8868, 19.55) -> (-2.0207, 19.05)
  line L30 (-5, 19.55) -> (-2.8868, 19.55)
  line L31 (-2.8868, 11.55) -> (-2.0207, 12.05)
  line L32 (-5, 11.55) -> (-2.8868, 11.55)
  line L33 (2, 20) -> (5, 25.1962)
  line L34 (5, 14.8038) -> (2, 20)
  line L35 (5, 58.875) -> (5, 0)
  line L36 (-4.7601, 58.875) -> (5, 58.875)
  circle C1 centre (0, 24.45) radius 1.7
  circle C2 centre (0, 15.55) radius 1.7
  circle C3 centre (0, 24.45) radius 4
  circle C4 centre (0, 15.55) radius 4
  point P1 (0, 0)
  point P14 (0, 20)
  point P15 (0, 20)
  point P16 (0, 24.45)
  point P23 (0, 24.45)
  point P25 (0, 15.55)
  point P30 (0, 15.55)
  point P12 (0, 15.55)
  point P13 (0, 24.45)
  point P33 (0, 15.55)
  point P35 (-5, 28.45)
  point P37 (-5, 20.45)
  point P38 (0, 20)
  point P39 (-5, 20)
  point P20 (-2.0207, 27.95)
  point P43 (-2.0207, 12.05)
  point P22 (-2.0207, 20.95)
  point P40 (-2.0207, 19.05)
  point P34 (-2.8868, 28.45)
  point P44 (-2.8868, 11.55)
  point P45 (-5, 11.55)
  point P36 (-2.8868, 20.45)
  point P41 (-2.8868, 19.55)
  point P42 (-5, 19.55)
  point P46 (5, 25.1962)
  point P48 (5, 14.8038)
  point P47 (2, 20)
  point P19 (2.0207, 27.95)
  point P26 (2.0207, 19.05)
  point P32 (0, 24.45)
  vertical L11
  coincident P1 L11
  midpoint L11 P14
  coincident P14 P15
  coincident P16 P23
  coincident P25 P30
  horizontal L14
  horizontal L22
  coincident P12 P30
  coincident P13 P23
  concentric C1 C3
  coincident P25 P33
  equal C3 C4
  perpendicular L15 L24
  coincident L5 P35
  perpendicular L5 L25
  perpendicular L16 L26
  coincident L5 P37
  perpendicular L5 L27
  coincident P15 P38
  coincident L5 P39
  perpendicular L5 L28
  symmetric P20 L28 P43
  symmetric P22 L28 P40
  symmetric P34 L28 P44
  symmetric P35 L28 P45
  symmetric P36 L28 P41
  symmetric P37 L28 P42
  coincident L7 P46
  coincident L7 P48
  coincident L28 P47
  dimension "d2167" distance P19 L17 = 7
  dimension "d2168" diameter C1 = 3.4
  dimension "d2169" distance P26 L20 = 7
  dimension "d2170" diameter C2 = 3.4 (= "d2168")
  dimension "d2171" distance P12 P13 = 8.9
  dimension "d2172" diameter C3 = 8
  dimension "d2173" distance L17 L22 = 1.9
  dimension "d2174" distance P32 L27 = 4
  dimension "d2175" distance P32 L25 = 4
  dimension "d2200" angle L28 L33 = 60
  dimension "d2201" distance L7 P47 = 3
  dimension "d2204" angle L28 L34 = 60 (= "d2200")
extrude "Extrude207" cut sketch "Side Mount" profile of C1 C2 against normal blind 12
chamfer "Chamfer24" distance 0.5
extrude "Extrude210" cut sketch "Side Mount" profile of L7 L33 L34 against normal blind 4
extrude "Extrude211" sketch "Elevation" profile of C5 C7 C9 to an object
sketch "Pogo Conn" plane through (0, 0, 0) normal (0, 1, 0) x axis (1, 0, 0)
  line L1 (-35, -110.5) -> (-9, -110.5)
  line L2 (-35, -170.5) -> (-35, -110.5)
  line L3 (-9, -170.5) -> (-35, -170.5)
  line L4 (-9, -110.5) -> (-9, -170.5)
  line L5 (-19.5, -159.25) -> (-24.5, -159.25)
  line L6 (-19.5, -112.75) -> (-19.5, -159.25)
  line L7 (-24.5, -112.75) -> (-19.5, -112.75)
  line L8 (-24.5, -159.25) -> (-24.5, -112.75)
  line L9 (-19.5, -112.75) -> (-24.5, -159.25)
  line L10 (-19.5, -159.25) -> (-24.5, -112.75)
  line L11 (-14, -156.5) -> (-30, -156.5)
  line L12 (-14, -115.5) -> (-14, -156.5)
  line L13 (-30, -115.5) -> (-14, -115.5)
  line L14 (-30, -156.5) -> (-30, -115.5)
  line L15 (-25.5, -153) -> (-35, -153)
  line L16 (-25.5, -119) -> (-25.5, -153)
  line L17 (-35, -119) -> (-25.5, -119)
  line L18 (-25.5, -136) -> (-22, -136)
  line L19 (-15, -172.5) -> (-29, -172.5)
  line L20 (-15, -160.25) -> (-15, -172.5)
  line L21 (-29, -160.25) -> (-15, -160.25)
  line L22 (-29, -172.5) -> (-29, -160.25)
  line L23 (-22, -160.25) -> (-22, -136)
  circle C1 centre (-30, -156.5) radius 1.7
  circle C2 centre (-30, -115.5) radius 1.7
  circle C3 centre (-14, -156.5) radius 1.7
  circle C4 centre (-14, -115.5) radius 1.7
  point P10 (-22, -136)
  point P14 (-14, -115.5)
  point P17 (-14, -115.5)
  point P11 (-30, -156.5)
  point P15 (-30, -156.5)
  point P13 (-14, -156.5)
  point P16 (-14, -156.5)
  point P12 (-30, -115.5)
  point P18 (-30, -115.5)
  point P19 (-35, -153)
  point P22 (-35, -119)
  point P23 (-22, -136)
  point P24 (-25.5, -136)
  point P29 (-22, -136)
  point P30 (-22, -160.25)
  point P4 (-35, -170.5)
  point P5 (-9, -170.5)
  point P3 (-35, -110.5)
  point P7 (-19.5, -159.25)
  point P8 (-19.5, -112.75)
  point P6 (-24.5, -159.25)
  point P1 (0, 0)
  point P2 (-9, -110.5)
  point P20 (-25.5, -153)
  point P21 (-25.5, -119)
  point P25 (-29, -172.5)
  point P26 (-15, -172.5)
  horizontal L1
  vertical L2
  horizontal L3
  vertical L4
  horizontal L5
  vertical L6
  horizontal L7
  vertical L8
  midpoint L10 P10
  equal C2 C4
  equal C1 C2
  equal C1 C3
  horizontal L11
  vertical L12
  horizontal L13
  vertical L14
  coincident P14 P17
  coincident P11 P15
  coincident P13 P16
  coincident P12 P18
  coincident L2 P19
  perpendicular L2 L15
  perpendicular L15 L16
  coincident L2 P22
  perpendicular L2 L17
  coincident P10 P23
  midpoint L16 P24
  horizontal L18
  horizontal L19
  vertical L20
  horizontal L21
  vertical L22
  coincident P10 P29
  midpoint L21 P30
  vertical L23
  dimension "d2245" distance P4 P5 = 26
  dimension "d2246" distance P3 P4 = 60
  dimension "d2247" distance L2 P10 = 13
  dimension "d2248" distance L1 P10 = 25.5
  dimension "d2249" distance P7 P8 = 46.5
  dimension "d2250" distance P6 P7 = 5
  dimension "d2251" distance P1 P10 = 136
  dimension "d2252" distance P1 P10 = 22
  dimension "d2253" diameter C1 = 3.4
  dimension "d2254" distance L2 L14 = 5
  dimension "d2255" distance L4 L12 = 5
  dimension "d2256" distance P2 L13 = 5
  dimension "d2257" distance L3 L11 = 14
  dimension "d2261" distance P20 P21 = 34
  dimension "d2262" distance P19 P20 = 9.5
  dimension "d2274" distance P25 P26 = 14
  dimension "d2275" distance L3 L19 = 2
  dimension "d2276" distance P7 L21 = 1
extrude "Extrude212" sketch "Pogo Conn" profile of L1 L2 L3 L4 C1 C2 C3 C4 L15 L16 L17 L20 L21 L22 to an object
extrude "Extrude214" sketch "Pogo Conn" profile of C2 C4 to an object
component_insert "Component Insert66"
joint "Assemble63" alignAngle 90 alignOffsetX 0 alignOffsetY 0 alignOffsetZ 0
